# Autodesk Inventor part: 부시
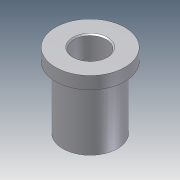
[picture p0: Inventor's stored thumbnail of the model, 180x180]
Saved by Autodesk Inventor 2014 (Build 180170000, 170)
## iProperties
Company: 한국ATC센터
Created: 2014-01
Part Number: 부시
Document SubType Name: Modeling
Designer: KYOUNG IL JANG
Density: 1 g/cm^3
Material: 일반
Mass: 8.58964 g
Surface Area: 43.3569 cm^2
Volume: 8.58964 cm^3
Vendor: CBT Solutions
Appearance: 기본값
Author: KYOUNG IL JANG
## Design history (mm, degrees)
sketch "스케치1"
  geometry: C1 r 11 at (0, 0) reference; C2 r 14 at (0, 0) reference; C3 r 11 at (0, 0) reference; 1 further point
  node "참조1"
  node "참조2"
extrude "돌출1" new body sketch "스케치1" distance "d0" = 5; taper "d1" = 0 deg
extrude "돌출2" join sketch "스케치1" distance "d2" = 25; taper "d3" = 0 deg
hole "구멍1" diameter "d6" = 13; stored, may be unused: countersink angle "d10" = 90 deg, drill point angle "d12" = 118 deg; dims "d4" = 10, "d5" = 10, "d7" = 6, "d8" = 4, "d9" = 2, "d11" = 8
chamfer "모따기1" distance "d13" = 0.5; stored, may be unused: second distance "d14" = 2, angle "d15" = 45 deg
node "솔리드1"
